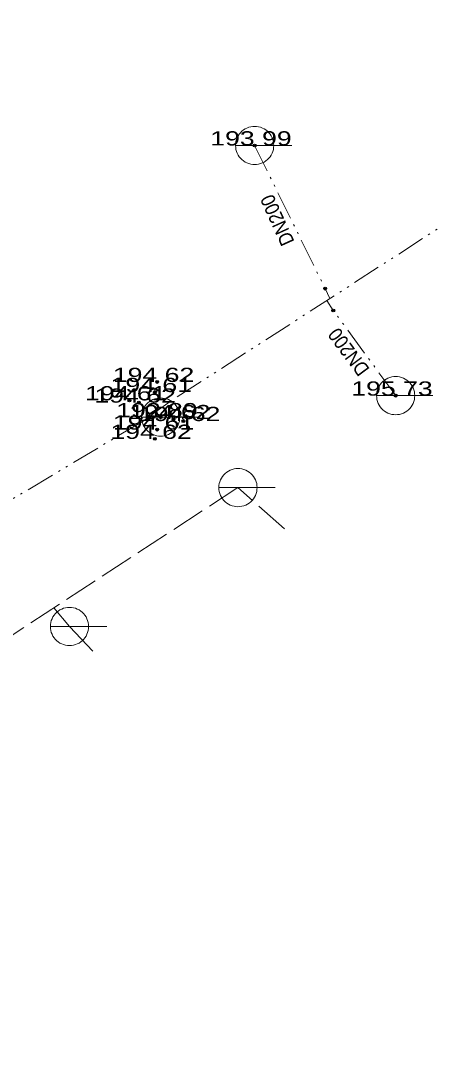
# Model space of a CAD drawing. Extents: x -688177 to -687620, y -1056713 to -1056287.
# Drawn here: x -687970.2 to -687948.5, y -1056547.5 to -1056493.1 of the extents above; entities that cross this region are included whole.
import ezdxf
from ezdxf.enums import TextEntityAlignment as Align

# ---------------------------------------------------------------- set-up
doc = ezdxf.new("R2010")
doc.units = 0
doc.header["$LTSCALE"] = 0.3
doc.header["$PDMODE"] = 32
doc.header["$PDSIZE"] = 0.15
for name, pattern in [('DASH_DOUBLE_DOT', [9.2, 5, -1.2, 0.3, -1.2, 0.3, -1.2]), ('DOTTED', [1.5, 0.3, -1.2]), ('LONG_DASHED', [7.5, 6, -1.5])]:
    doc.linetypes.add(name, pattern=pattern)
for name, color, linetype in [('1', 7, 'Continuous'), ('19', 7, 'Continuous'), ('3', 7, 'Continuous')]:
    doc.layers.add(name, color=color, linetype=linetype)
for name, color, linetype, lineweight in [('12', 7, 'Continuous', 13), ('46', 7, 'DOTTED', 13), ('50', 7, 'LONG_DASHED', 13), ('51', 7, 'DASH_DOUBLE_DOT', 13)]:
    doc.layers.add(name, color=color, linetype=linetype, lineweight=lineweight)

msp = doc.modelspace()

# ---------------------------------------------------------------- linework, layer by layer
at = {"layer": '1'}
for p in [(-687957.88, -1056499.68), (-687954.16, -1056507.23), (-687953.73, -1056508.38), (-687963.02, -1056512.15), (-687963.14, -1056512.68), (-687964.49, -1056513.12), (-687963.99, -1056513.24), (-687950.44, -1056512.87), (-687962.84, -1056514.01), (-687962.16, -1056514.11), (-687961.64, -1056514.21), (-687963.02, -1056514.66), (-687963.15, -1056515.15)]:
    msp.add_point(p, dxfattribs=at)
at = {"layer": '12'}
for p, q in [((-687958.888, -1056499.68), (-687955.912, -1056499.68)), ((-687951.448, -1056512.87), (-687948.472, -1056512.87)), ((-687963.848, -1056514), (-687960.872, -1056514)), ((-687959.768, -1056517.72), (-687956.792, -1056517.72)), ((-687968.658, -1056525.04), (-687965.682, -1056525.04))]:
    msp.add_line(p, q, dxfattribs=at)
for points in [[(-687957.88, -1056498.672), (-687957.985, -1056498.678), (-687958.089, -1056498.694), (-687958.191, -1056498.722), (-687958.29, -1056498.76), (-687958.384, -1056498.807), (-687958.472, -1056498.865), (-687958.554, -1056498.931), (-687958.629, -1056499.006), (-687958.695, -1056499.088), (-687958.753, -1056499.176), (-687958.8, -1056499.27), (-687958.838, -1056499.369), (-687958.866, -1056499.471), (-687958.882, -1056499.575), (-687958.888, -1056499.68), (-687958.882, -1056499.785), (-687958.866, -1056499.89), (-687958.838, -1056499.992), (-687958.8, -1056500.09), (-687958.753, -1056500.184), (-687958.695, -1056500.273), (-687958.629, -1056500.355), (-687958.554, -1056500.429), (-687958.472, -1056500.495), (-687958.384, -1056500.553), (-687958.29, -1056500.601), (-687958.191, -1056500.639), (-687958.089, -1056500.666), (-687957.985, -1056500.682), (-687957.88, -1056500.688), (-687957.775, -1056500.682), (-687957.67, -1056500.666), (-687957.568, -1056500.639), (-687957.47, -1056500.601), (-687957.376, -1056500.553), (-687957.287, -1056500.495), (-687957.205, -1056500.429), (-687957.131, -1056500.355), (-687957.065, -1056500.273), (-687957.007, -1056500.184), (-687956.959, -1056500.09), (-687956.921, -1056499.992), (-687956.894, -1056499.89), (-687956.878, -1056499.785), (-687956.872, -1056499.68), (-687956.878, -1056499.575), (-687956.894, -1056499.471), (-687956.921, -1056499.369), (-687956.959, -1056499.27), (-687957.007, -1056499.176), (-687957.065, -1056499.088), (-687957.131, -1056499.006), (-687957.205, -1056498.931), (-687957.287, -1056498.865), (-687957.376, -1056498.807), (-687957.47, -1056498.76), (-687957.568, -1056498.722), (-687957.67, -1056498.694), (-687957.775, -1056498.678)], [(-687950.44, -1056511.862), (-687950.545, -1056511.868), (-687950.649, -1056511.884), (-687950.751, -1056511.912), (-687950.85, -1056511.95), (-687950.944, -1056511.997), (-687951.032, -1056512.055), (-687951.114, -1056512.121), (-687951.189, -1056512.196), (-687951.255, -1056512.278), (-687951.313, -1056512.366), (-687951.36, -1056512.46), (-687951.398, -1056512.559), (-687951.426, -1056512.661), (-687951.442, -1056512.765), (-687951.448, -1056512.87), (-687951.442, -1056512.975), (-687951.426, -1056513.08), (-687951.398, -1056513.182), (-687951.36, -1056513.28), (-687951.313, -1056513.374), (-687951.255, -1056513.463), (-687951.189, -1056513.545), (-687951.114, -1056513.619), (-687951.032, -1056513.685), (-687950.944, -1056513.743), (-687950.85, -1056513.791), (-687950.751, -1056513.829), (-687950.649, -1056513.856), (-687950.545, -1056513.872), (-687950.44, -1056513.878), (-687950.335, -1056513.872), (-687950.23, -1056513.856), (-687950.128, -1056513.829), (-687950.03, -1056513.791), (-687949.936, -1056513.743), (-687949.847, -1056513.685), (-687949.765, -1056513.619), (-687949.691, -1056513.545), (-687949.625, -1056513.463), (-687949.567, -1056513.374), (-687949.519, -1056513.28), (-687949.481, -1056513.182), (-687949.454, -1056513.08), (-687949.438, -1056512.975), (-687949.432, -1056512.87), (-687949.438, -1056512.765), (-687949.454, -1056512.661), (-687949.481, -1056512.559), (-687949.519, -1056512.46), (-687949.567, -1056512.366), (-687949.625, -1056512.278), (-687949.691, -1056512.196), (-687949.765, -1056512.121), (-687949.847, -1056512.055), (-687949.936, -1056511.997), (-687950.03, -1056511.95), (-687950.128, -1056511.912), (-687950.23, -1056511.884), (-687950.335, -1056511.868)], [(-687962.84, -1056512.992), (-687962.945, -1056512.998), (-687963.049, -1056513.014), (-687963.151, -1056513.042), (-687963.25, -1056513.08), (-687963.344, -1056513.127), (-687963.432, -1056513.185), (-687963.514, -1056513.251), (-687963.589, -1056513.326), (-687963.655, -1056513.408), (-687963.713, -1056513.496), (-687963.76, -1056513.59), (-687963.798, -1056513.689), (-687963.826, -1056513.791), (-687963.842, -1056513.895), (-687963.848, -1056514), (-687963.842, -1056514.105), (-687963.826, -1056514.21), (-687963.798, -1056514.312), (-687963.76, -1056514.41), (-687963.713, -1056514.504), (-687963.655, -1056514.593), (-687963.589, -1056514.675), (-687963.514, -1056514.749), (-687963.432, -1056514.815), (-687963.344, -1056514.873), (-687963.25, -1056514.921), (-687963.151, -1056514.959), (-687963.049, -1056514.986), (-687962.945, -1056515.002), (-687962.84, -1056515.008), (-687962.735, -1056515.002), (-687962.63, -1056514.986), (-687962.528, -1056514.959), (-687962.43, -1056514.921), (-687962.336, -1056514.873), (-687962.247, -1056514.815), (-687962.165, -1056514.749), (-687962.091, -1056514.675), (-687962.025, -1056514.593), (-687961.967, -1056514.504), (-687961.919, -1056514.41), (-687961.881, -1056514.312), (-687961.854, -1056514.21), (-687961.838, -1056514.105), (-687961.832, -1056514), (-687961.838, -1056513.895), (-687961.854, -1056513.791), (-687961.881, -1056513.689), (-687961.919, -1056513.59), (-687961.967, -1056513.496), (-687962.025, -1056513.408), (-687962.091, -1056513.326), (-687962.165, -1056513.251), (-687962.247, -1056513.185), (-687962.336, -1056513.127), (-687962.43, -1056513.08), (-687962.528, -1056513.042), (-687962.63, -1056513.014), (-687962.735, -1056512.998)], [(-687958.76, -1056516.712), (-687958.865, -1056516.718), (-687958.969, -1056516.734), (-687959.071, -1056516.762), (-687959.17, -1056516.8), (-687959.264, -1056516.847), (-687959.352, -1056516.905), (-687959.434, -1056516.971), (-687959.509, -1056517.046), (-687959.575, -1056517.128), (-687959.633, -1056517.216), (-687959.68, -1056517.31), (-687959.718, -1056517.409), (-687959.746, -1056517.511), (-687959.762, -1056517.615), (-687959.768, -1056517.72), (-687959.762, -1056517.825), (-687959.746, -1056517.93), (-687959.718, -1056518.032), (-687959.68, -1056518.13), (-687959.633, -1056518.224), (-687959.575, -1056518.313), (-687959.509, -1056518.395), (-687959.434, -1056518.469), (-687959.352, -1056518.535), (-687959.264, -1056518.593), (-687959.17, -1056518.641), (-687959.071, -1056518.679), (-687958.969, -1056518.706), (-687958.865, -1056518.722), (-687958.76, -1056518.728), (-687958.655, -1056518.722), (-687958.55, -1056518.706), (-687958.448, -1056518.679), (-687958.35, -1056518.641), (-687958.256, -1056518.593), (-687958.167, -1056518.535), (-687958.085, -1056518.469), (-687958.011, -1056518.395), (-687957.945, -1056518.313), (-687957.887, -1056518.224), (-687957.839, -1056518.13), (-687957.801, -1056518.032), (-687957.774, -1056517.93), (-687957.758, -1056517.825), (-687957.752, -1056517.72), (-687957.758, -1056517.615), (-687957.774, -1056517.511), (-687957.801, -1056517.409), (-687957.839, -1056517.31), (-687957.887, -1056517.216), (-687957.945, -1056517.128), (-687958.011, -1056517.046), (-687958.085, -1056516.971), (-687958.167, -1056516.905), (-687958.256, -1056516.847), (-687958.35, -1056516.8), (-687958.448, -1056516.762), (-687958.55, -1056516.734), (-687958.655, -1056516.718)], [(-687967.65, -1056524.032), (-687967.755, -1056524.038), (-687967.859, -1056524.054), (-687967.961, -1056524.082), (-687968.06, -1056524.12), (-687968.154, -1056524.167), (-687968.242, -1056524.225), (-687968.324, -1056524.291), (-687968.399, -1056524.366), (-687968.465, -1056524.448), (-687968.523, -1056524.536), (-687968.57, -1056524.63), (-687968.608, -1056524.729), (-687968.636, -1056524.831), (-687968.652, -1056524.935), (-687968.658, -1056525.04), (-687968.652, -1056525.145), (-687968.636, -1056525.25), (-687968.608, -1056525.352), (-687968.57, -1056525.45), (-687968.523, -1056525.544), (-687968.465, -1056525.633), (-687968.399, -1056525.715), (-687968.324, -1056525.789), (-687968.242, -1056525.855), (-687968.154, -1056525.913), (-687968.06, -1056525.961), (-687967.961, -1056525.999), (-687967.859, -1056526.026), (-687967.755, -1056526.042), (-687967.65, -1056526.048), (-687967.545, -1056526.042), (-687967.44, -1056526.026), (-687967.338, -1056525.999), (-687967.24, -1056525.961), (-687967.146, -1056525.913), (-687967.057, -1056525.855), (-687966.975, -1056525.789), (-687966.901, -1056525.715), (-687966.835, -1056525.633), (-687966.777, -1056525.544), (-687966.729, -1056525.45), (-687966.691, -1056525.352), (-687966.664, -1056525.25), (-687966.648, -1056525.145), (-687966.642, -1056525.04), (-687966.648, -1056524.935), (-687966.664, -1056524.831), (-687966.691, -1056524.729), (-687966.729, -1056524.63), (-687966.777, -1056524.536), (-687966.835, -1056524.448), (-687966.901, -1056524.366), (-687966.975, -1056524.291), (-687967.057, -1056524.225), (-687967.146, -1056524.167), (-687967.24, -1056524.12), (-687967.338, -1056524.082), (-687967.44, -1056524.054), (-687967.545, -1056524.038)]]:
    msp.add_lwpolyline(points, close=True, dxfattribs=at)
at = {"layer": '46', "linetype": 'DASH_DOUBLE_DOT'}
for points in [[(-687931.68, -1056493.1), (-687932.67, -1056494.04), (-687962.33, -1056513.18), (-687963.07, -1056513.7)], [(-687963.07, -1056513.7), (-687963.77, -1056514.21), (-687996.49, -1056533.74), (-687997.29, -1056534.15)]]:
    msp.add_lwpolyline(points, dxfattribs=at)
at = {"layer": '50'}
for points in [[(-687956.31, -1056519.9), (-687958.76, -1056517.72), (-687973.44, -1056527.3), (-687990.03, -1056545.42), (-687993.39, -1056560.73)], [(-687966.41, -1056526.34), (-687967.65, -1056525.04), (-687968.48, -1056524.06)]]:
    msp.add_lwpolyline(points, dxfattribs=at)
at = {"layer": '51'}
for points in [[(-687957.88, -1056499.68), (-687954.16, -1056507.23), (-687953.91, -1056507.75)], [(-687950.44, -1056512.87), (-687953.73, -1056508.38), (-687954.07, -1056507.85)]]:
    msp.add_lwpolyline(points, dxfattribs=at)

# ---------------------------------------------------------------- texts
at = {"layer": '19', "width": 0.9}
for rotation, p in [(114.42, (-687955.765, -1056504.748)), (126.738, (-687951.78, -1056511.471))]:
    msp.add_text('DN200', height=0.75, rotation=rotation, dxfattribs=at).set_placement(p)
at = {"layer": '3', "width": 1.4}
for s, p in [('193 99 ', (-687957.88, -1056499.68)), ('194 62 ', (-687963.02, -1056512.15)), ('194 61 ', (-687963.14, -1056512.68)), ('195 73 ', (-687950.44, -1056512.87)), ('194 61 ', (-687964.49, -1056513.12)), ('194 62 ', (-687963.99, -1056513.24)), ('192 89 ', (-687962.84, -1056514.01)), ('194 62 ', (-687962.16, -1056514.11)), ('194 62 ', (-687961.64, -1056514.21)), ('194 62 ', (-687963.15, -1056515.15)), ('194 61 ', (-687963.02, -1056514.66))]:
    msp.add_text(s, height=0.75, dxfattribs=at).set_placement(p, align=Align.CENTER)

doc.saveas('drawing.dxf')
